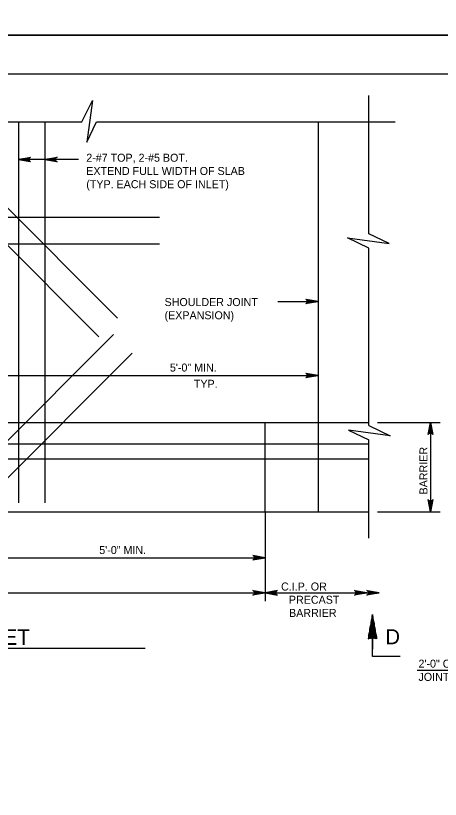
# Model space of a CAD drawing. Extents: x 638167 to 640248, y 296544 to 298920.
# Drawn here: x 639299 to 639462.1, y 296845.2 to 297146 of the extents above; entities that cross this region are included whole.
import ezdxf

# ---------------------------------------------------------------- set-up
doc = ezdxf.new("R2010")
doc.units = 0
doc.layers.add('1', color=7, linetype='Continuous')
doc.layers.add('PLT-BNDY', color=7, linetype='Continuous')

msp = doc.modelspace()

# ---------------------------------------------------------------- linework, layer by layer
at = {"layer": '1'}
for p, q in [((639832.78, 297123.48), (639046.78, 297123.48)), ((639434.62, 297062.3), (639434.62, 297115.36)), ((639163.42, 297105.2), (639324.43, 297105.2)), ((639300, 297105.2), (639300, 296958.97)), ((639310.16, 297105.2), (639310.16, 296958.97)), ((639329.97, 297105.2), (639444.78, 297105.2)), ((639415.14, 297105.2), (639415.14, 296955.59)), ((639323.06, 297090.78), (639300, 297090.78)), ((639280.6, 297087.41), (639338.07, 297029.94)), ((639273.41, 297080.23), (639330.89, 297022.75)), ((639133.63, 297068.62), (639354.18, 297068.62)), ((639133.63, 297058.46), (639354.18, 297058.46)), ((639434.62, 296988.7), (639434.62, 297056.76)), ((639399.63, 297036.23), (639415.14, 297036.23)), ((639336.56, 297023.63), (639279.08, 296966.16)), ((639343.74, 297016.45), (639286.27, 296958.97)), ((639293.22, 297007.84), (639415.14, 297007.84)), ((639073.51, 296989.88), (639434.62, 296989.88)), ((639394.82, 296955.59), (639394.82, 296989.88)), ((639437.93, 296989.88), (639462.05, 296989.88)), ((639458.37, 296989.88), (639458.37, 296955.59)), ((639073.51, 296981.62), (639434.62, 296981.62)), ((639434.62, 296945.43), (639434.62, 296983.16)), ((639073.51, 296975.91), (639434.62, 296975.91)), ((639073.51, 296955.59), (639434.62, 296955.59)), ((639394.82, 296955.59), (639394.82, 296921.29)), ((639437.93, 296955.59), (639462.05, 296955.59)), ((639293.22, 296937.97), (639394.82, 296937.97)), ((639049.21, 296924.45), (639438.6, 296924.45)), ((639436.02, 296907.13), (639436.02, 296902.85)), ((639436.04, 296900.09), (639436.04, 296907.3)), ((639158.3, 296903.18), (639348.75, 296903.18)), ((639446.68, 296900.09), (639436.04, 296900.09)), ((639506.17, 296894.73), (639453.17, 296894.73))]:
    msp.add_line(p, q, dxfattribs=at)
for points in [[(639324.43, 297105.2), (639328.42, 297113.37), (639326.25, 297097.38), (639329.97, 297105.2)], [(639300, 297090.78), (639304.69, 297091.66), (639304.51, 297091.53), (639304.33, 297091.41), (639304.24, 297091.25), (639304.15, 297091.09), (639304.12, 297090.93), (639304.09, 297090.78), (639304.12, 297090.62), (639304.15, 297090.46), (639304.24, 297090.3), (639304.33, 297090.15), (639304.51, 297090.02), (639304.69, 297089.9), (639300, 297090.78), (639304.51, 297090.02), (639304.33, 297090.15), (639300, 297090.78), (639304.24, 297090.3), (639304.15, 297090.46), (639300, 297090.78), (639304.12, 297090.62), (639304.09, 297090.78), (639300, 297090.78), (639304.12, 297090.93), (639304.15, 297091.09), (639300, 297090.78), (639304.24, 297091.25), (639304.33, 297091.41), (639300, 297090.78), (639304.51, 297091.53)], [(639310.16, 297090.78), (639314.85, 297091.66), (639314.67, 297091.53), (639314.49, 297091.41), (639314.4, 297091.25), (639314.31, 297091.09), (639314.28, 297090.93), (639314.25, 297090.78), (639314.28, 297090.62), (639314.31, 297090.46), (639314.4, 297090.3), (639314.49, 297090.15), (639314.67, 297090.02), (639314.85, 297089.9), (639310.16, 297090.78), (639314.67, 297090.02), (639314.49, 297090.15), (639310.16, 297090.78), (639314.4, 297090.3), (639314.31, 297090.46), (639310.16, 297090.78), (639314.28, 297090.62), (639314.25, 297090.78), (639310.16, 297090.78), (639314.28, 297090.93), (639314.31, 297091.09), (639310.16, 297090.78), (639314.4, 297091.25), (639314.49, 297091.41), (639310.16, 297090.78), (639314.67, 297091.53)], [(639434.62, 297056.76), (639426.45, 297060.76), (639442.43, 297058.59), (639434.62, 297062.3)], [(639415.14, 297036.23), (639410.45, 297035.35), (639410.63, 297035.48), (639410.81, 297035.6), (639410.9, 297035.76), (639410.99, 297035.92), (639411.02, 297036.08), (639411.05, 297036.23), (639411.02, 297036.39), (639410.99, 297036.55), (639410.9, 297036.71), (639410.81, 297036.86), (639410.63, 297036.99), (639410.45, 297037.12), (639415.14, 297036.23), (639410.63, 297036.99), (639410.81, 297036.86), (639415.14, 297036.23), (639410.9, 297036.71), (639410.99, 297036.55), (639415.14, 297036.23), (639411.02, 297036.39), (639411.05, 297036.23), (639415.14, 297036.23), (639411.02, 297036.08), (639410.99, 297035.92), (639415.14, 297036.23), (639410.9, 297035.76), (639410.81, 297035.6), (639415.14, 297036.23), (639410.63, 297035.48)], [(639415.14, 297007.84), (639410.45, 297006.96), (639410.63, 297007.09), (639410.81, 297007.21), (639410.9, 297007.37), (639410.99, 297007.53), (639411.02, 297007.69), (639411.05, 297007.84), (639411.02, 297008), (639410.99, 297008.16), (639410.9, 297008.32), (639410.81, 297008.47), (639410.63, 297008.6), (639410.45, 297008.72), (639415.14, 297007.84), (639410.63, 297008.6), (639410.81, 297008.47), (639415.14, 297007.84), (639410.9, 297008.32), (639410.99, 297008.16), (639415.14, 297007.84), (639411.02, 297008), (639411.05, 297007.84), (639415.14, 297007.84), (639411.02, 297007.69), (639410.99, 297007.53), (639415.14, 297007.84), (639410.9, 297007.37), (639410.81, 297007.21), (639415.14, 297007.84), (639410.63, 297007.09)], [(639434.62, 296988.7), (639442.78, 296984.7), (639426.8, 296986.88), (639434.62, 296983.16)], [(639458.37, 296989.88), (639459.25, 296985.18), (639459.13, 296985.36), (639459, 296985.54), (639458.84, 296985.64), (639458.68, 296985.73), (639458.53, 296985.76), (639458.37, 296985.78), (639458.21, 296985.76), (639458.05, 296985.73), (639457.9, 296985.64), (639457.74, 296985.54), (639457.61, 296985.36), (639457.49, 296985.18), (639458.37, 296989.88), (639457.61, 296985.36), (639457.74, 296985.54), (639458.37, 296989.88), (639457.9, 296985.64), (639458.05, 296985.73), (639458.37, 296989.88), (639458.21, 296985.76), (639458.37, 296985.78), (639458.37, 296989.88), (639458.53, 296985.76), (639458.68, 296985.73), (639458.37, 296989.88), (639458.84, 296985.64), (639459, 296985.54), (639458.37, 296989.88), (639459.13, 296985.36)], [(639458.37, 296955.59), (639457.49, 296960.29), (639457.61, 296960.1), (639457.74, 296959.92), (639457.9, 296959.83), (639458.05, 296959.74), (639458.21, 296959.71), (639458.37, 296959.68), (639458.53, 296959.71), (639458.68, 296959.74), (639458.84, 296959.83), (639459, 296959.92), (639459.13, 296960.1), (639459.25, 296960.29), (639458.37, 296955.59), (639459.13, 296960.1), (639459, 296959.92), (639458.37, 296955.59), (639458.84, 296959.83), (639458.68, 296959.74), (639458.37, 296955.59), (639458.53, 296959.71), (639458.37, 296959.68), (639458.37, 296955.59), (639458.21, 296959.71), (639458.05, 296959.74), (639458.37, 296955.59), (639457.9, 296959.83), (639457.74, 296959.92), (639458.37, 296955.59), (639457.61, 296960.1)], [(639394.82, 296937.97), (639390.13, 296938.85), (639390.31, 296938.73), (639390.49, 296938.6), (639390.58, 296938.44), (639390.67, 296938.29), (639390.7, 296938.13), (639390.73, 296937.97), (639390.7, 296937.81), (639390.67, 296937.66), (639390.58, 296937.5), (639390.49, 296937.34), (639390.31, 296937.21), (639390.13, 296937.09), (639394.82, 296937.97), (639390.31, 296937.21), (639390.49, 296937.34), (639394.82, 296937.97), (639390.58, 296937.5), (639390.67, 296937.66), (639394.82, 296937.97), (639390.7, 296937.81), (639390.73, 296937.97), (639394.82, 296937.97), (639390.7, 296938.13), (639390.67, 296938.29), (639394.82, 296937.97), (639390.58, 296938.44), (639390.49, 296938.6), (639394.82, 296937.97), (639390.31, 296938.73)], [(639394.82, 296924.45), (639390.13, 296923.57), (639390.31, 296923.69), (639390.49, 296923.82), (639390.58, 296923.98), (639390.67, 296924.13), (639390.7, 296924.29), (639390.73, 296924.45), (639390.7, 296924.61), (639390.67, 296924.76), (639390.58, 296924.92), (639390.49, 296925.08), (639390.31, 296925.2), (639390.13, 296925.33), (639394.82, 296924.45), (639390.31, 296925.2), (639390.49, 296925.08), (639394.82, 296924.45), (639390.58, 296924.92), (639390.67, 296924.76), (639394.82, 296924.45), (639390.7, 296924.61), (639390.73, 296924.45), (639394.82, 296924.45), (639390.7, 296924.29), (639390.67, 296924.13), (639394.82, 296924.45), (639390.58, 296923.98), (639390.49, 296923.82), (639394.82, 296924.45), (639390.31, 296923.69)], [(639394.82, 296924.45), (639399.52, 296923.57), (639399.34, 296923.69), (639399.16, 296923.82), (639399.07, 296923.98), (639398.97, 296924.13), (639398.95, 296924.29), (639398.92, 296924.45), (639398.95, 296924.61), (639398.97, 296924.76), (639399.07, 296924.92), (639399.16, 296925.08), (639399.34, 296925.2), (639399.52, 296925.33), (639394.82, 296924.45), (639399.34, 296925.2), (639399.16, 296925.08), (639394.82, 296924.45), (639399.07, 296924.92), (639398.97, 296924.76), (639394.82, 296924.45), (639398.95, 296924.61), (639398.92, 296924.45), (639394.82, 296924.45), (639398.95, 296924.29), (639398.97, 296924.13), (639394.82, 296924.45), (639399.07, 296923.98), (639399.16, 296923.82), (639394.82, 296924.45), (639399.34, 296923.69)], [(639433.86, 296924.45), (639429.16, 296923.57), (639429.34, 296923.69), (639429.52, 296923.82), (639429.62, 296923.98), (639429.71, 296924.13), (639429.74, 296924.29), (639429.76, 296924.45), (639429.74, 296924.61), (639429.71, 296924.76), (639429.62, 296924.92), (639429.52, 296925.08), (639429.34, 296925.2), (639429.16, 296925.33), (639433.86, 296924.45), (639429.34, 296925.2), (639429.52, 296925.08), (639433.86, 296924.45), (639429.62, 296924.92), (639429.71, 296924.76), (639433.86, 296924.45), (639429.74, 296924.61), (639429.76, 296924.45), (639433.86, 296924.45), (639429.74, 296924.29), (639429.71, 296924.13), (639433.86, 296924.45), (639429.62, 296923.98), (639429.52, 296923.82), (639433.86, 296924.45), (639429.34, 296923.69)], [(639438.6, 296924.45), (639433.91, 296923.57), (639434.09, 296923.69), (639434.27, 296923.82), (639434.36, 296923.98), (639434.46, 296924.13), (639434.48, 296924.29), (639434.51, 296924.45), (639434.48, 296924.61), (639434.46, 296924.76), (639434.36, 296924.92), (639434.27, 296925.08), (639434.09, 296925.2), (639433.91, 296925.33), (639438.6, 296924.45), (639434.09, 296925.2), (639434.27, 296925.08), (639438.6, 296924.45), (639434.36, 296924.92), (639434.46, 296924.76), (639438.6, 296924.45), (639434.48, 296924.61), (639434.51, 296924.45), (639438.6, 296924.45), (639434.48, 296924.29), (639434.46, 296924.13), (639438.6, 296924.45), (639434.36, 296923.98), (639434.27, 296923.82), (639438.6, 296924.45), (639434.09, 296923.69)], [(639437.67, 296906.82), (639436.02, 296916.13), (639434.42, 296906.82), (639434.63, 296906.92), (639434.61, 296907.91), (639434.82, 296909.11), (639434.84, 296906.99), (639435.06, 296907.03), (639435.07, 296910.56), (639435.28, 296911.81), (639435.28, 296907.09), (639435.51, 296907.13), (639435.5, 296913.09), (639435.75, 296914.51), (639435.74, 296907.16), (639435.95, 296907.15), (639435.95, 296915.71), (639436.03, 296916.12), (639436.24, 296914.93), (639436.18, 296907.17), (639436.4, 296907.14), (639436.45, 296913.74), (639436.66, 296912.56), (639436.66, 296907.1), (639436.86, 296907.1), (639436.89, 296911.23), (639437.13, 296909.88), (639437.11, 296907.03), (639437.34, 296906.97), (639437.33, 296908.77), (639437.57, 296907.4), (639437.51, 296906.88)]]:
    msp.add_lwpolyline(points, dxfattribs=at)
msp.add_arc((639436.05, 296902.82), 4.31, 67.8762, 112.1238, dxfattribs=at)
at = {"layer": 'PLT-BNDY'}
for points in [[(639007.78, 297732.48), (639848.78, 297732.48), (639848.78, 297138.48), (639007.78, 297138.48)], [(639007.78, 297138.48), (639848.78, 297138.48), (639848.78, 296544.48), (639007.78, 296544.48)]]:
    msp.add_lwpolyline(points, close=True, dxfattribs=at)

# ---------------------------------------------------------------- texts
at = {"layer": '1'}
for s, height, rotation, p in [('2-#7 TOP, 2-#5 BOT.', 3.072, 360, (639326.09, 297089.92)), ('EXTEND FULL WIDTH OF SLAB', 3.072, 360, (639326.09, 297084.84)), ('(TYP. EACH SIDE OF INLET)', 3.072, 360, (639326.09, 297079.77)), ('SHOULDER JOINT', 3.072, 360, (639356.17, 297034.53)), ('(EXPANSION)', 3.072, 360, (639356.17, 297029.46)), ('BARRIER', 3.072, 90, (639457.18, 296962.22)), ('C.I.P. OR', 3.072, 360, (639400.93, 296925.36)), ('PRECAST', 3.072, 360, (639403.94, 296920.29)), ('BARRIER', 3.072, 360, (639404, 296915.22)), ('D', 5.77, 360, (639441.04, 296904.74))]:
    msp.add_text(s, height=height, rotation=rotation, dxfattribs=at).set_placement(p)
for s, height, p in [('5\'-0" MIN.', 3.072, (639358.22, 297009.4)), ('TYP.', 3.072, (639367.43, 297003.15)), ('5\'-0" MIN.', 3.072, (639331.08, 296939.36)), ('PLAN - SHOULDER DETAILS AT INLET', 6, (639158.66, 296904.51)), ('2\'-0" OPEN', 3.072, (639453.72, 296895.75)), ('JOINT IN BARRIER', 3.072, (639453.72, 296890.68))]:
    msp.add_text(s, height=height, dxfattribs=at).set_placement(p)

doc.saveas('drawing.dxf')
